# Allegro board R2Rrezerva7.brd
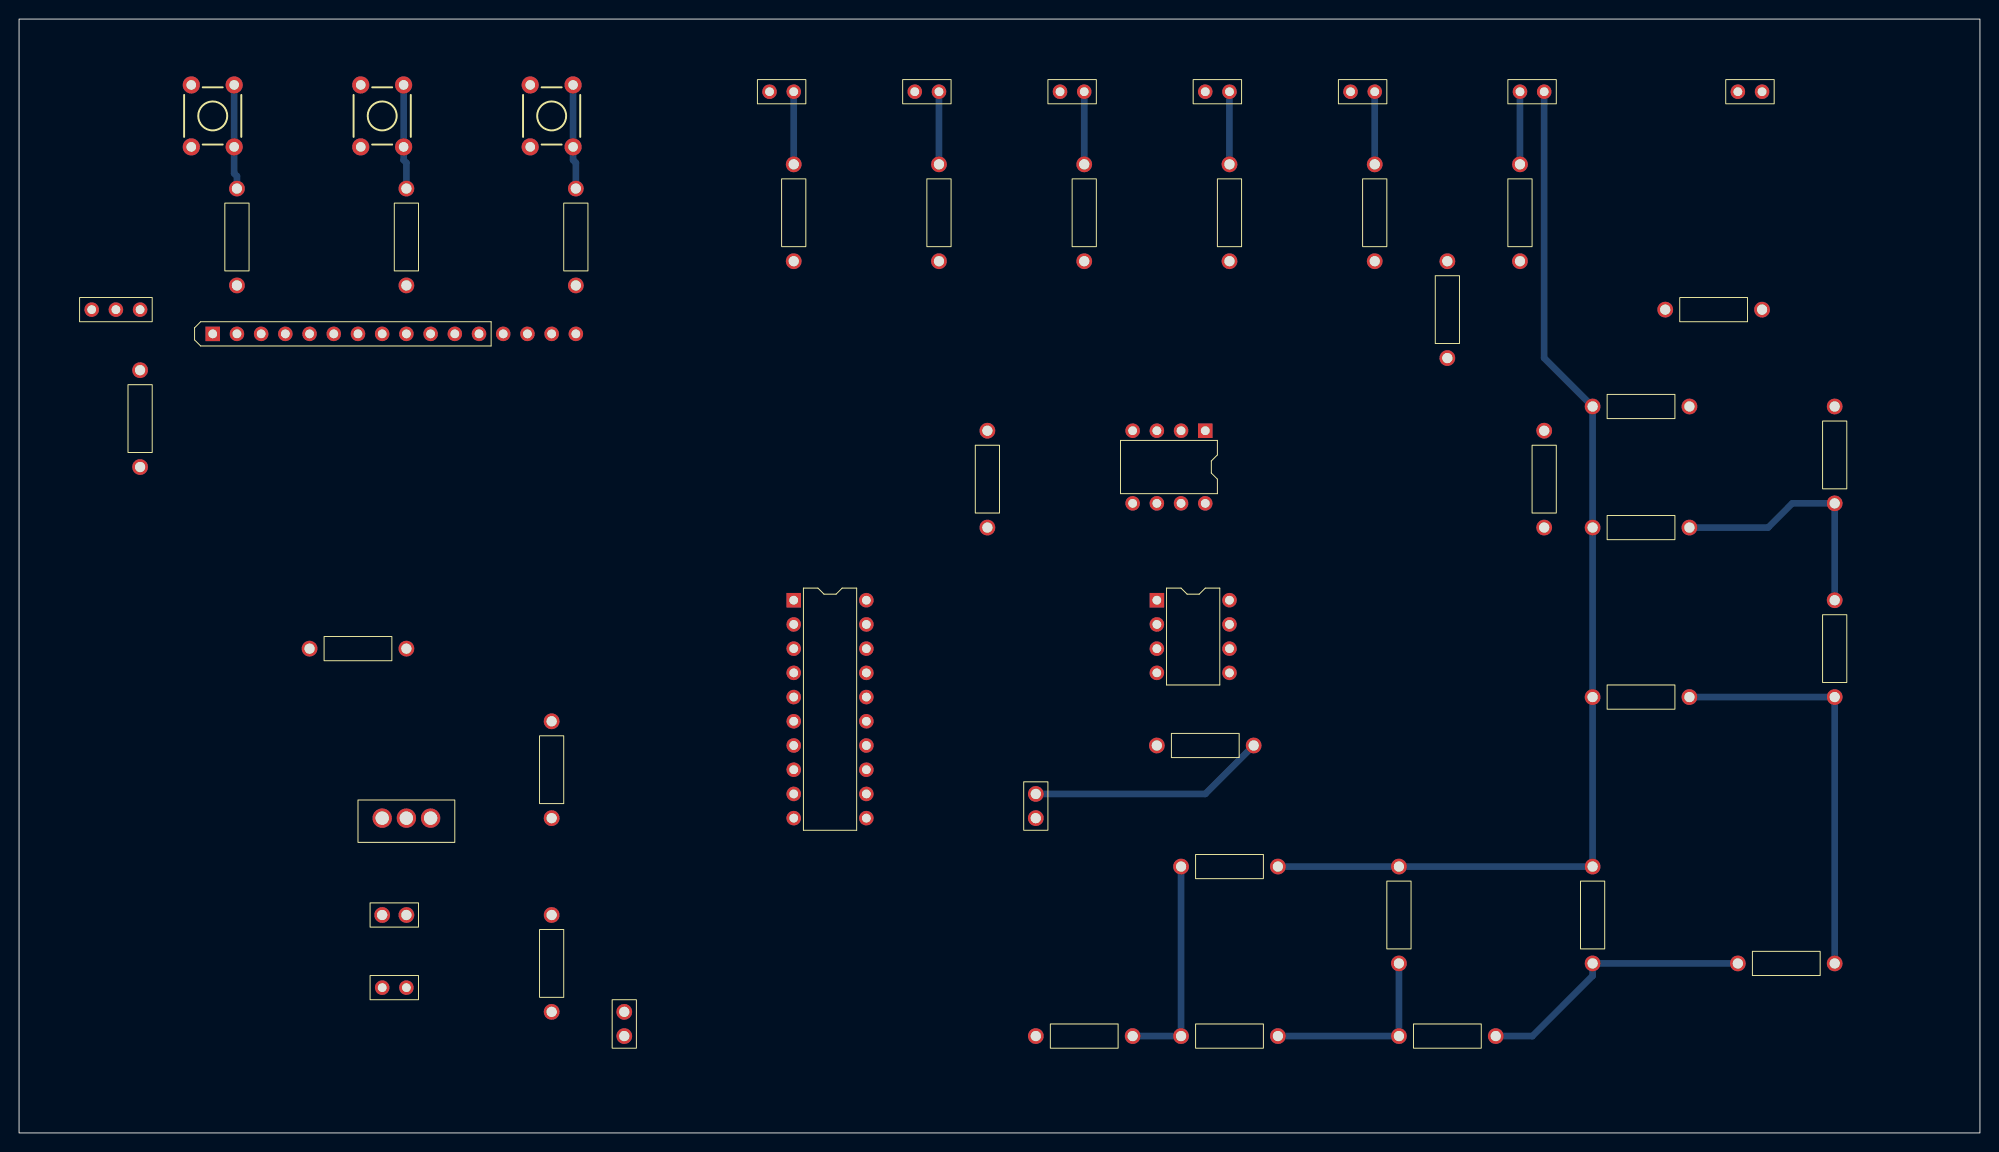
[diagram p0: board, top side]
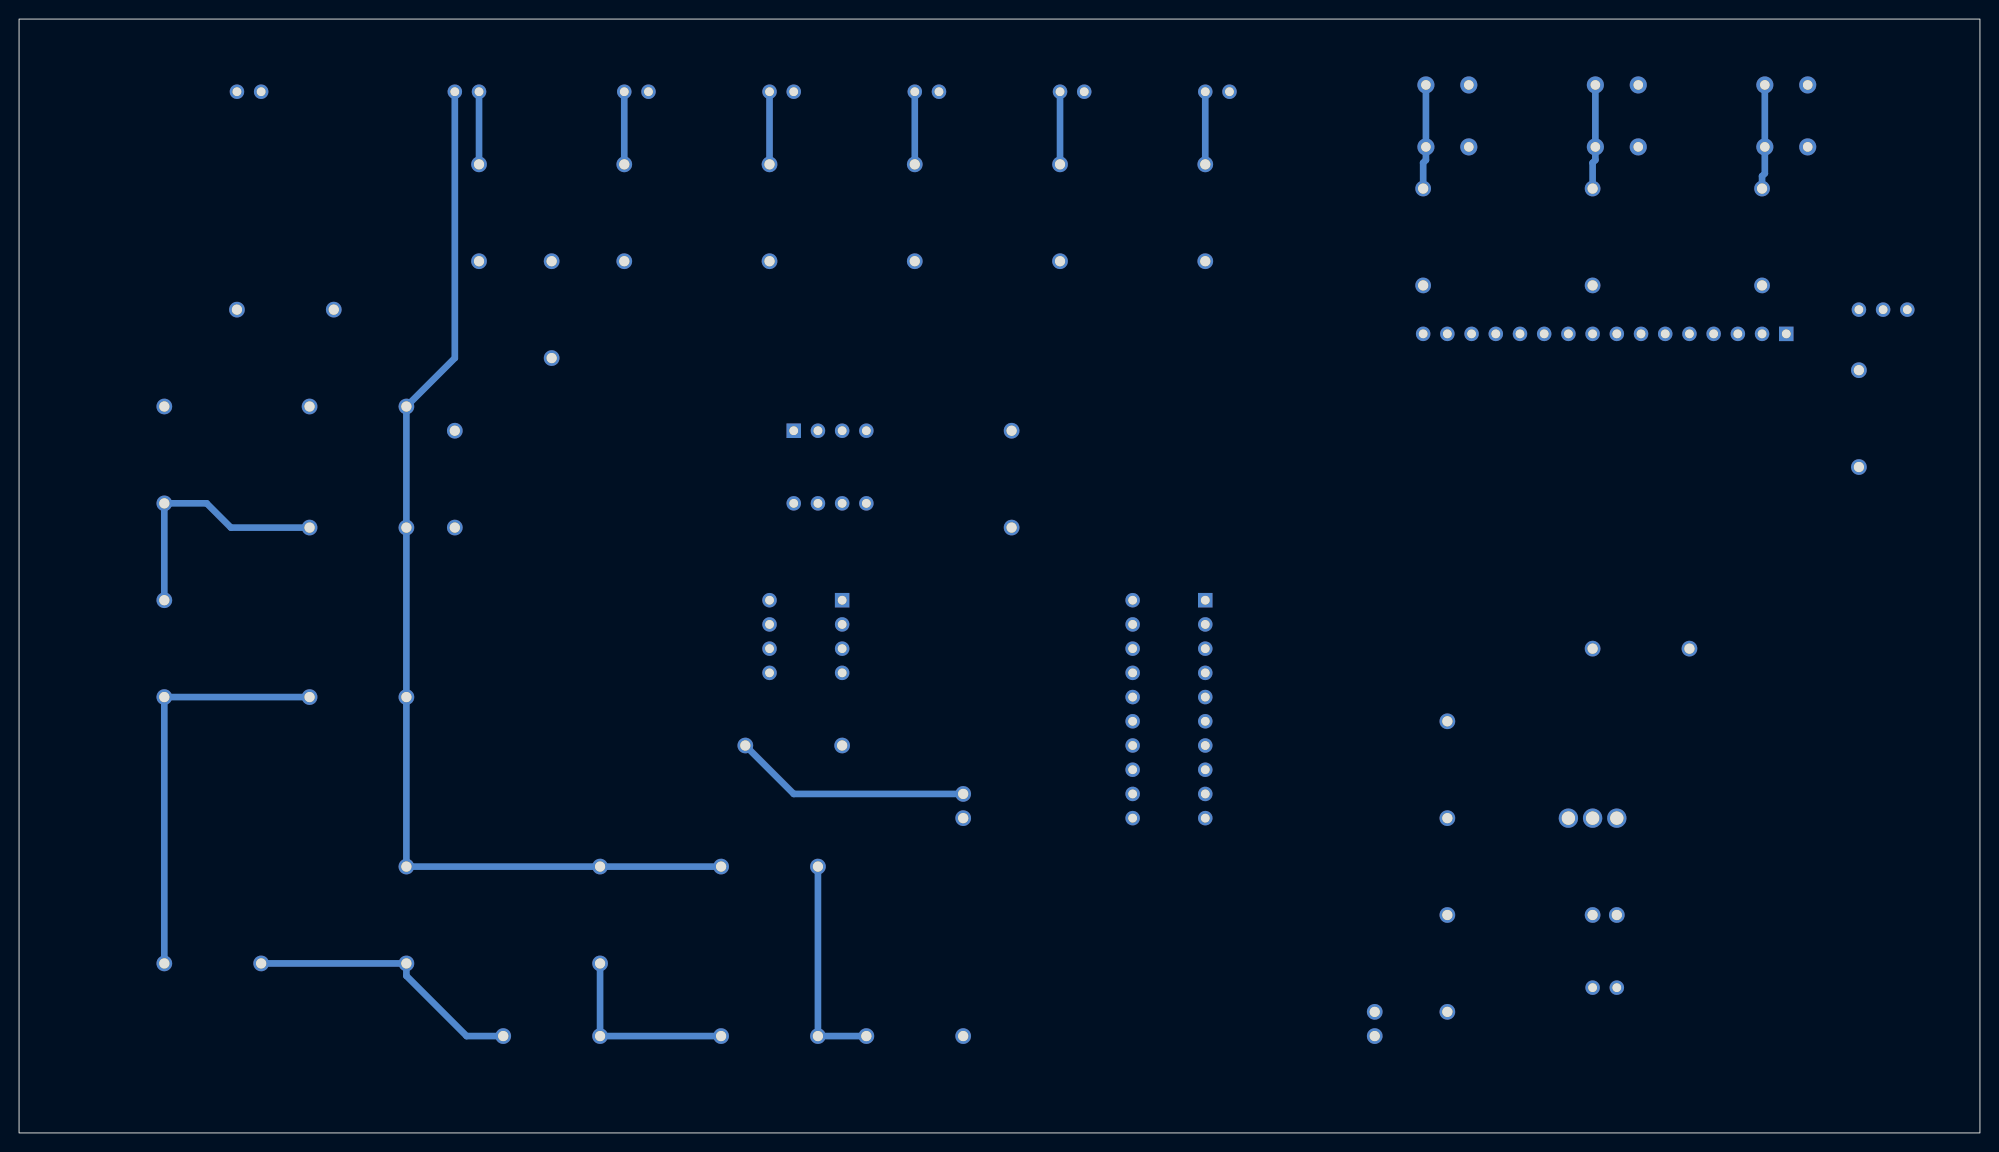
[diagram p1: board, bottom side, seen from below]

Outline 205.74 x 116.84 mm; copper layers: TOP, BOTTOM. Coordinates in mm from the lower left corner of the outline.
Outline path: rectangle 0,0 205.74,116.84

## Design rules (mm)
nets with their own width: min track width 0.7; nets N00328 N00332 N00336 N00340 N00355 N00470 N01662 N006340 N006500 N006660 N006820 N006980 N007140 N20855 N23488 N23661 N24189 N24193 N25824 N25853 N28143 N35057 N35516 N35592 N35638 N35656 N35674 N35692 N35721 N209781 SW1 SW2 SW3
nets with their own width: min track width 1; nets 0 9V V+ V- VCC

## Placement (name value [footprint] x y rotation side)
C3  10nf  [CAPCK05]  106.68 35.56 180 top
C4  10u  [CAPCK05]  38.1 22.86 270 top
C5  10u  [CAPCK05]  63.5 10.16 0 top
D1  MLED81  [JUMPER2]  78.74 109.22 0 top
D2  MLED81  [JUMPER2]  93.98 109.22 0 top
D3  MLED81  [JUMPER2]  109.22 109.22 0 top
D4  MLED81  [JUMPER2]  124.46 109.22 0 top
D5  MLED81  [JUMPER2]  139.7 109.22 0 top
D6  MLED81  [JUMPER2]  160.02 109.22 180 top
J1  Speaker  [JUMPER2]  180.34 109.22 0 top
J2  LCD 1602  [SIP16]  20.32 83.82 90 top
J3  ALIMENTARE 9V  [JUMPER2]  40.64 15.24 180 top
R2  1k  [RES400]  190.5 66.04 0 top
R3  1k  [RES400]  190.5 45.72 0 top
R4  1k  [RES400]  180.34 17.78 270 top
R5  1k  [RES400]  144.78 10.16 270 top
R6  1k  [RES400]  121.92 10.16 270 top
R7  2k  [RES400]  132.08 27.94 90 top
R8  2k  [RES400]  144.78 27.94 180 top
R9  2k  [RES400]  165.1 27.94 180 top
R10  2k  [RES400]  165.1 45.72 270 top
R11  2k  [RES400]  165.1 63.5 270 top
R12  2k  [RES400]  165.1 76.2 270 top
R13  2k  [RES400]  106.68 10.16 270 top
R14  470  [RES400]  157.48 91.44 0 top
R15  470  [RES400]  142.24 91.44 0 top
R16  470  [RES400]  127 91.44 0 top
R17  470  [RES400]  111.76 91.44 0 top
R18  470  [RES400]  96.52 91.44 0 top
R19  470  [RES400]  81.28 91.44 0 top
R20  10k  [RES400]  149.86 81.28 0 top
R22  10k  [RES400]  160.02 63.5 0 top
R23  1k  [RES400]  30.48 50.8 270 top
R24  470  [RES400]  55.88 33.02 0 top
R25  150  [RES400]  55.88 12.7 0 top
R26  33k  [RES400]  119.38 40.64 270 top
R27  10k  [RES400]  101.6 73.66 180 top
R28  10k  [RES400]  182.88 86.36 90 top
R29  1k  [JUMPER3]  7.62 86.36 0 top
R30  10k  [RES400]  22.86 99.06 180 top
R33  1k  [RES400]  12.7 80.01 180 top
R34  10k  [RES400]  40.64 99.06 180 top
R35  10k  [RES400]  58.42 99.06 180 top
SW7  SW_TC_SPST  [SW_SCHURTER_13019301L]  20.32 106.68 180 top
SW8  SW_TC_SPST  [SW_SCHURTER_13019301L]  38.1 106.68 180 top
SW9  SW_TC_SPST  [SW_SCHURTER_13019301L]  55.88 106.68 180 top
U1  MSP430G2553  [DIP20]  81.28 55.88 0 top
U7  LM317K  [TO220AB]  43.18 33.02 0 top
U9  LM358  [DIP8_3]  124.46 73.66 270 top
U10  LM358  [DIP8_3]  119.38 55.88 0 top

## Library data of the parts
C3-C5 = C: Tolerance: ***; User Part Number: ***
D1-D6 = MLED81: User Part Number: ***
J1 J3 = CON2: User Part Number: ***
J2 = CON16: User Part Number: ***
R2-R20 R22-R28 R30 R33-R35 = R: Tolerance: ***; User Part Number: ***
R29 = POT: User Part Number: ***
SW7-SW9 = SW_TC_SPST
U1 = MSP430G2553_4: Tolerance: ***; User Part Number: ***
U7 = LM317T
U9 = LM358: Tolerance: ***; User Part Number: ***
U10 = LM358_0: Tolerance: ***; User Part Number: ***

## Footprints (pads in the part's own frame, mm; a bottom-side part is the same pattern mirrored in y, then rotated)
CAPCK05
  round 1.651 hole 1.067: 1(0,0) 2(0,2.54)
DIP8_3
  rect 1.524x1.524 hole 0.914: 1(0,0)
  round 1.524 hole 0.914: 2(0,-2.54) 3(0,-5.08) 4(0,-7.62) 5(7.62,-7.62) 6(7.62,-5.08) 7(7.62,-2.54) 8(7.62,0)
DIP20
  rect 1.524x1.524 hole 0.914: 1(0,0)
  round 1.524 hole 0.914: 2(0,-2.54) 3(0,-5.08) 4(0,-7.62) 5(0,-10.16) 6(0,-12.7) 7(0,-15.24) 8(0,-17.78) 9(0,-20.32) 10(0,-22.86) 11(7.62,-22.86) 12(7.62,-20.32) 13(7.62,-17.78) 14(7.62,-15.24) 15(7.62,-12.7) 16(7.62,-10.16) 17(7.62,-7.62) 18(7.62,-5.08) 19(7.62,-2.54) 20(7.62,0)
JUMPER2
  round 1.524 hole 0.914: 1(0,0) 2(2.54,0)
JUMPER3
  round 1.524 hole 0.914: 1(0,0) 2(2.54,0) 3(5.08,0)
RES400
  round 1.651 hole 1.067: 1(0,0) 2(0,10.16)
SIP16
  rect 1.524x1.524 hole 0.914: 1(0,0)
  round 1.524 hole 0.914: 2(0,-2.54) 3(0,-5.08) 4(0,-7.62) 5(0,-10.16) 6(0,-12.7) 7(0,-15.24) 8(0,-17.78) 9(0,-20.32) 10(0,-22.86) 11(0,-25.4) 12(0,-27.94) 13(0,-30.48) 14(0,-33.02) 15(0,-35.56) 16(0,-38.1)
SW_SCHURTER_13019301L
  round 1.8 hole 1: 1(-2.25,-3.25) 2(-2.25,3.25) 3(2.25,3.25) 4(2.25,-3.25)
TO220AB
  round 2.032 hole 1.397: 1(0,0) 2(-2.54,0) 3(-5.08,0)

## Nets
9V: C4.1 J3.2 U9.8(V+)
VCC: C5.2 J2.2 J2.16 R24.2 R30.2 R33.1 R34.2 R35.2 U1.1(DVCC) U7.3(OUT)
0: C3.2 C5.1 J2.1 J2.5 J3.1 R13.1 R14.1 R15.1 R16.1 R17.1 R18.1 R19.1 R20.2 R23.1 R29.1 SW7.3 SW8.3 SW9.3 U1.20(GROUND) U9.4(V-) U9.5(+)
SW1: R30.1 SW7.1 SW7.2 U1.8(P2_0/CS(B0))
SW2: R34.1 SW8.1 SW8.2 U1.9(P2_1)
SW3: R35.1 SW9.1 SW9.2 U1.10(P2_2)
V+: U10.8(V+)
V-: U10.4(V-)
N00328: R2.1 R3.2 R11.2
N00332: R3.1 R4.2 R10.2
N00336: R4.1 R5.2 R9.2
N00340: R5.1 R6.2 R8.2
N00355: R2.2 R12.2 U10.3(+)
N00470: R6.1 R7.2 R13.2
N01662: D1.1(A) D2.1(A) D3.1(A) D4.1(A) D5.1(A) D6.1(A) R7.1 R8.1 R9.1 R10.1 R11.1 R12.1 U1.2(P1_0/A0/RED_LED) U1.3(P1_1/A1/RXD) U1.4(P1_2/A2/TXD) U1.5(P1_3/A3/PUSH2) U1.6(P1_4/A4) U1.7(P1_5/A5/SCK(B0))
N006340: D6.2(C) R14.2
N006500: D5.2(C) R15.2
N006660: D4.2(C) R16.2
N006820: D3.2(C) R17.2
N006980: D2.2(C) R18.2
N007140: D1.2(C) R19.2
N20855: R23.2 R25.1 U7.1(ADJ)
N23488: C3.1 R26.2 U9.3(+)
N23661: R26.1 U10.1(OUT) U10.2(-)
N24189: R20.1 R27.2 U9.2(-)
N24193: J1.1 R22.2 R27.1 U9.1(OUT)
N25824: R22.1 R28.2 U9.6(-)
N25853: J1.2 R28.1 U9.7(OUT)
N28143: C4.2 U7.2(IN)
N35057: J2.3 R29.2(T) R29.3(2)
N35516: J2.4 U1.11(P2_3)
N35592: J2.6 U1.12(P2_4)
N35638: J2.11 U1.13(P2_5)
N35656: J2.12 U1.14(P1_6/A6/SCL/MISO(B0)/GREEN LED)
N35674: J2.13 U1.15(P1_7/A7/SDA/MOSE(B0))
N35692: J2.14 U1.18(P2_7/XOUT)
N35721: J2.15 R33.2
N209781: R24.1 R25.2

Pads without a net: J2 7 8 9 10; SW7 4; SW8 4; SW9 4; U1 16 17 19; U10 5 6 7

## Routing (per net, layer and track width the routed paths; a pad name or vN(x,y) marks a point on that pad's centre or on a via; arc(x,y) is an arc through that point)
SW1: length 11
  BOTTOM w0.7: SW7.1 SW7.2 22.57,100.65 22.86,100.36 R30.1
SW2: length 11
  BOTTOM w0.7: SW8.1 SW8.2 40.35,102.05 40.64,101.76 R34.1
SW3: length 11
  BOTTOM w0.7: R35.1 58.42,101.76 58.13,102.05 SW9.2 SW9.1
N00328: length 26.5
  BOTTOM w0.7: R11.2 183.52,63.5 186.06,66.04 R2.1 R3.2
N00332: length 43.2
  BOTTOM w0.7: R10.2 R3.1 R4.2
N00336: length 29.3
  BOTTOM w0.7: R4.1 R9.2 165.1,16.48 158.78,10.16 R5.2
N00340: length 20.3
  BOTTOM w0.7: R8.2 R5.1 R6.2
N00470: length 22.9
  BOTTOM w0.7: R13.2 R6.1 R7.2
N01662: length 116.4
  BOTTOM w0.7: R7.1 R8.1 R9.1 R10.1 R11.1 R12.1 160.02,81.28 D6.1
N006340: length 7.6
  BOTTOM w0.7: R14.2 D6.2
N006500: length 7.6
  BOTTOM w0.7: R15.2 D5.2
N006660: length 7.6
  BOTTOM w0.7: R16.2 D4.2
N006820: length 7.6
  BOTTOM w0.7: R17.2 D3.2
N006980: length 7.6
  BOTTOM w0.7: R18.2 D2.2
N007140: length 7.6
  BOTTOM w0.7: R19.2 D1.2
N23488: length 25
  BOTTOM w0.7: C3.1 124.46,35.56 R26.2
